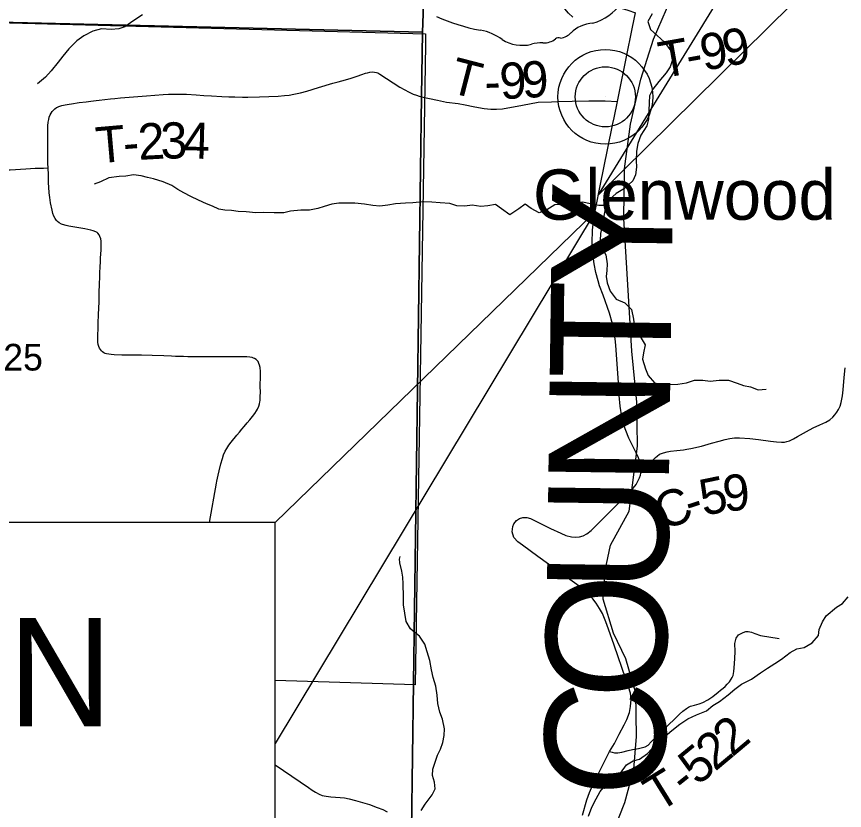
# Model space of a CAD drawing. Extents: x 0 to 34, y 0 to 22.
# Drawn here: x 4.145 to 5.445, y 16.906 to 18.153 of the extents above; entities that cross this region are included whole.
import ezdxf

# ---------------------------------------------------------------- set-up
doc = ezdxf.new("R2010")
doc.units = 0
for name, color, linetype in [('GM_X_Corporation', 7, 'Continuous'), ('GM_X_County_Road', 7, 'Continuous'), ('GM_X_County_Road_Text', 7, 'Continuous'), ('GM_X_County_Text', 7, 'Continuous'), ('GM_X_Minor_River', 7, 'Continuous'), ('GM_X_Rail_Line', 7, 'Continuous'), ('GM_X_Section_Text', 7, 'Continuous'), ('GM_X_State_Route', 7, 'Continuous'), ('GM_X_State_Shield', 7, 'Continuous'), ('GM_X_Township_Road', 7, 'Continuous'), ('GM_X_Township_Road_Text', 7, 'Continuous'), ('GM_X_Unincorporated', 7, 'Continuous'), ('GM_X_Unincorporated_Location', 7, 'Continuous'), ('GM_X_Unincorporated_Text', 7, 'Continuous'), ('SH_Data', 7, 'Continuous'), ('SH_Text', 7, 'Continuous')]:
    doc.layers.add(name, color=color, linetype=linetype)

msp = doc.modelspace()

# ---------------------------------------------------------------- linework, layer by layer
at = {"layer": 'GM_X_Corporation'}
for points in [[(4.0508, 18.1454), (4.7823, 18.128), (4.7905, 18.3604), (4.8074, 19.5455), (4.8169, 20.042), (4.8194, 20.1261), (5.11, 20.116), (6.0551, 20.0845), (6.4901, 20.0752), (6.7204, 20.0659), (7.3691, 20.0515), (7.3901, 20.051), (7.814, 20.0425), (8.4311, 20.028), (8.4311, 21.3734), (2.7987, 21.3734)], [(4.7905, 18.3604), (4.7823, 18.128), (4.7806, 18.0273), (4.765, 16.8754), (4.756, 16.2274), (4.759, 16.0879), (4.9206, 16.0842), (4.928, 16.0841), (4.9731, 16.0831), (4.975, 16.083), (5.0347, 16.0817), (5.0373, 16.0816), (6.4668, 16.045), (6.4721, 16.0449), (6.6873, 16.0404), (6.6909, 16.0403), (6.7034, 16.04), (6.9699, 16.0345), (6.9736, 16.0344), (7.8043, 16.0135), (7.8077, 16.0135), (8.4311, 16.0029), (8.4311, 20.028)], [(3.7652, 16.1115), (4.1576, 16.1007), (4.1598, 16.0996), (4.1627, 16.0987), (4.1674, 16.0981), (4.2356, 16.0972), (4.2455, 16.0972), (4.2746, 16.0965), (4.2814, 16.0964), (4.2857, 16.0964), (4.2943, 16.0963), (4.3121, 16.0959), (4.3257, 16.0953), (4.3338, 16.0949), (4.3467, 16.0944), (4.3559, 16.0941), (4.3665, 16.0934), (4.723, 16.0888), (4.759, 16.0879), (4.756, 16.2274), (4.765, 16.8754), (4.7806, 18.0273), (4.7823, 18.128), (4.7905, 18.3604)], [(4.7905, 18.3604), (4.7823, 18.128), (4.7806, 18.0273), (4.765, 16.8754), (4.756, 16.2274), (4.759, 16.0879), (4.723, 16.0888), (4.3665, 16.0934), (4.3559, 16.0941), (4.3467, 16.0944), (4.3338, 16.0949), (4.3257, 16.0953), (4.3121, 16.0959), (4.2943, 16.0963), (4.2857, 16.0964), (4.2814, 16.0964), (4.2746, 16.0965), (4.2455, 16.0972), (4.2356, 16.0972), (4.1674, 16.0981), (4.1627, 16.0987), (4.1598, 16.0996), (4.1576, 16.1007), (3.7652, 16.1115)], [(3.763, 17.3579), (3.7781, 18.1522), (4.7872, 18.1255), (4.7868, 18.1081), (4.7707, 17.1031), (4.5509, 17.1099)], [(3.7652, 16.1115), (4.1576, 16.1007), (4.1598, 16.0996), (4.1627, 16.0987), (4.1674, 16.0981), (4.2356, 16.0972), (4.2455, 16.0972), (4.2746, 16.0965), (4.2814, 16.0964), (4.2857, 16.0964), (4.2943, 16.0963), (4.3121, 16.0959), (4.3257, 16.0953), (4.3338, 16.0949), (4.3467, 16.0944), (4.3559, 16.0941), (4.3665, 16.0934), (4.723, 16.0888), (4.759, 16.0879), (4.756, 16.2274), (4.765, 16.8754), (4.7806, 18.0273), (4.7823, 18.128), (4.0508, 18.1454)]]:
    msp.add_lwpolyline(points, dxfattribs=at)
at = {"layer": 'GM_X_County_Road'}
for points in [[(5.125, 17.4354), (5.1277, 17.4396), (5.1323, 17.4445), (5.1378, 17.4501), (5.1448, 17.4572), (5.1482, 17.4604), (5.1506, 17.4625), (5.1546, 17.4652), (5.1608, 17.4675), (5.1663, 17.469), (5.1718, 17.4699), (5.1817, 17.471), (5.1921, 17.4721), (5.1975, 17.473), (5.2036, 17.4742), (5.2205, 17.4782), (5.2358, 17.4825), (5.2481, 17.4859), (5.2573, 17.4882), (5.265, 17.4899), (5.2722, 17.4908), (5.2802, 17.491), (5.2964, 17.4901), (5.3097, 17.4884), (5.3287, 17.4859), (5.3379, 17.4848), (5.3461, 17.4843), (5.3506, 17.4843), (5.3542, 17.4851), (5.3586, 17.4864), (5.3649, 17.4896), (5.3709, 17.493), (5.3849, 17.5011), (5.3956, 17.5066), (5.4061, 17.5113), (5.4155, 17.5155), (5.4216, 17.5192), (5.4265, 17.5236), (5.4297, 17.5272), (5.4327, 17.5315), (5.4352, 17.5355), (5.4378, 17.5409), (5.4397, 17.5466), (5.4418, 17.557), (5.4428, 17.5667), (5.4443, 17.5858), (5.446, 17.6012)], [(4.5509, 16.9773), (4.6034, 16.9418), (4.6093, 16.9377), (4.6141, 16.9347), (4.62, 16.9314), (4.6249, 16.9294), (4.631, 16.9281), (4.6384, 16.9274), (4.6458, 16.9269), (4.6532, 16.9262), (4.6599, 16.9254), (4.6672, 16.924), (4.6769, 16.9216), (4.6883, 16.9185), (4.6989, 16.9151), (4.7112, 16.9106), (4.7198, 16.9071), (4.7271, 16.9036)]]:
    msp.add_lwpolyline(points, dxfattribs=at)
at = {"layer": 'GM_X_Minor_River'}
for points in [[(5.1427, 18.1572), (5.1359, 18.1451), (5.1405, 18.1326), (5.1507, 18.1232), (5.1621, 18.1126), (5.172, 18.099), (5.1751, 18.0865), (5.1709, 18.0736), (5.1649, 18.0641), (5.1532, 18.0508), (5.1438, 18.0386), (5.1389, 18.028), (5.1382, 18.0177), (5.1378, 18.0045), (5.1371, 17.9916), (5.1345, 17.981), (5.1251, 17.9665), (5.1206, 17.9532), (5.1183, 17.9411), (5.118, 17.9267), (5.1184, 17.9161), (5.1165, 17.9039), (5.1124, 17.8945), (5.0996, 17.8827), (5.0863, 17.875), (5.0758, 17.8655), (5.0697, 17.8534), (5.0668, 17.8393), (5.0649, 17.8249), (5.0619, 17.812), (5.0612, 17.801), (5.0639, 17.7904), (5.07, 17.7783), (5.0723, 17.7643), (5.0719, 17.7541), (5.0708, 17.7446), (5.072, 17.7343), (5.0769, 17.7215), (5.0864, 17.7086), (5.1001, 17.703), (5.1103, 17.6928), (5.1134, 17.6776), (5.1154, 17.6625), (5.1241, 17.65), (5.1317, 17.6371), (5.1291, 17.6246), (5.1276, 17.6144), (5.1322, 17.5996), (5.1364, 17.589), (5.1467, 17.5777), (5.1584, 17.5747), (5.169, 17.5747), (5.183, 17.5755), (5.1966, 17.5775), (5.2091, 17.5817), (5.2224, 17.5817), (5.2337, 17.5803), (5.2481, 17.5814), (5.2625, 17.5815), (5.2765, 17.577), (5.286, 17.5732), (5.297, 17.5714), (5.3091, 17.5665), (5.3216, 17.5673)], [(4.3427, 18.1553), (4.3291, 18.1468), (4.3152, 18.1368), (4.3054, 18.1333), (4.2936, 18.1325), (4.2784, 18.1335), (4.2648, 18.1296), (4.2505, 18.1223), (4.2395, 18.1146), (4.2271, 18.1023), (4.2177, 18.0905), (4.2106, 18.081), (4.1993, 18.0676), (4.1903, 18.0576), (4.1778, 18.0469)], [(4.7776, 17.8613), (4.7672, 17.86), (4.7554, 17.8596), (4.7399, 17.8587), (4.7281, 17.8567), (4.7156, 17.8551), (4.7043, 17.8561), (4.6913, 17.8583), (4.6762, 17.8597), (4.6512, 17.8595), (4.6402, 17.8579), (4.6281, 17.8544), (4.6182, 17.8512), (4.605, 17.8489), (4.5913, 17.8484), (4.575, 17.8471), (4.5644, 17.8447), (4.5493, 17.8446), (4.5334, 17.8449), (4.5205, 17.8444), (4.5053, 17.8462), (4.4932, 17.8464), (4.4825, 17.8479), (4.4719, 17.8485), (4.4624, 17.8504), (4.4525, 17.8548), (4.443, 17.8586), (4.4305, 17.8645), (4.4187, 17.8701), (4.4077, 17.8761), (4.3981, 17.8813), (4.3886, 17.8873), (4.3753, 17.8929), (4.3601, 17.8981), (4.3506, 17.8999), (4.3407, 17.9025), (4.3286, 17.9039), (4.3165, 17.9023), (4.3063, 17.9015), (4.29, 17.8995), (4.2767, 17.8933), (4.2669, 17.8894)], [(5.071, 17.8559), (5.0591, 17.856), (5.0459, 17.8586), (5.0337, 17.8612), (5.019, 17.8589), (5.005, 17.8573), (4.9902, 17.8569), (4.9774, 17.8493), (4.9656, 17.8447), (4.9531, 17.8514), (4.9436, 17.8582), (4.9334, 17.8506), (4.9195, 17.8415), (4.9066, 17.8505), (4.8971, 17.8577), (4.885, 17.8554), (4.874, 17.8546), (4.8604, 17.8564), (4.849, 17.8549), (4.8361, 17.8552), (4.8251, 17.8593), (4.81, 17.8604), (4.7971, 17.8611), (4.7846, 17.8615), (4.7776, 17.8613)], [(4.7466, 17.2945), (4.7461, 17.3009)], [(4.7462, 17.3006), (4.7472, 17.3047)], [(4.7676, 17.1872), (4.7634, 17.1913), (4.7567, 17.2027), (4.7527, 17.2285), (4.7523, 17.2414), (4.7521, 17.2619), (4.7513, 17.2721), (4.7497, 17.2816), (4.7466, 17.2945)], [(5.0427, 16.8969), (5.0483, 16.9109), (5.0551, 16.9239), (5.0611, 16.9356), (5.0713, 16.9474), (5.0819, 16.9547), (5.0932, 16.9642), (5.1026, 16.9775), (5.1128, 16.9839), (5.123, 16.9863), (5.1355, 16.9954), (5.148, 17.0091), (5.1604, 17.0201), (5.174, 17.0312), (5.1865, 17.0411), (5.199, 17.0498), (5.2126, 17.0559), (5.2281, 17.0624), (5.2379, 17.0704), (5.2485, 17.0769), (5.2621, 17.0876), (5.2726, 17.0963), (5.2832, 17.1043), (5.2987, 17.112), (5.3127, 17.1219), (5.324, 17.1295), (5.3354, 17.1364), (5.346, 17.1436), (5.3596, 17.1539), (5.3701, 17.1596), (5.3815, 17.1619), (5.3943, 17.1692), (5.4038, 17.1806), (5.4053, 17.1901), (5.4105, 17.2018), (5.4162, 17.2113), (5.432, 17.225), (5.4419, 17.2311), (5.4505, 17.2414)], [(4.7802, 16.9055), (4.7863, 16.9157), (4.7976, 16.9302), (4.8021, 16.94), (4.8013, 16.9503), (4.7982, 16.9609), (4.7986, 16.9707), (4.802, 16.9814), (4.8061, 16.9924), (4.8106, 17.0022), (4.8144, 17.0125), (4.8166, 17.0235), (4.817, 17.0341), (4.8135, 17.0492), (4.8097, 17.0602), (4.8066, 17.0739), (4.8051, 17.0871), (4.8031, 17.1008), (4.7993, 17.1148), (4.7962, 17.1269), (4.7939, 17.1413), (4.7897, 17.1549), (4.7859, 17.167), (4.7775, 17.1795), (4.7676, 17.1872)]]:
    msp.add_lwpolyline(points, dxfattribs=at)
at = {"layer": 'GM_X_Rail_Line'}
msp.add_lwpolyline([(5.0755, 16.8561), (5.1001, 16.9183), (5.1142, 16.9707), (5.1181, 17.0221), (5.1174, 17.09), (5.1017, 17.1439), (5.0823, 17.1842), (5.0659, 17.2376), (5.0692, 17.2827), (5.0776, 17.3226), (5.1068, 17.3761), (5.12, 17.4779), (5.1188, 17.5469), (5.1112, 17.6272), (5.0984, 17.8358), (5.0997, 17.9137), (5.1091, 17.9837), (5.125, 18.0544), (5.1451, 18.1171), (5.1789, 18.1962)], dxfattribs=at)
at = {"layer": 'GM_X_State_Route'}
for points in [[(5.0884, 18.0194), (5.1042, 18.0973), (5.1099, 18.1258), (5.112, 18.1363), (5.1165, 18.1584)], [(5.0337, 16.8985), (5.0405, 16.9223), (5.0446, 16.9341), (5.049, 16.9451), (5.0759, 16.9982), (5.0839, 17.0112), (5.0911, 17.0257), (5.099, 17.0405), (5.1032, 17.0489), (5.1072, 17.0597), (5.1091, 17.0691), (5.1099, 17.0802), (5.1087, 17.0901), (5.1059, 17.0999), (5.1014, 17.112), (5.0831, 17.1653), (5.0744, 17.1904), (5.0702, 17.2023), (5.0647, 17.2151), (5.0604, 17.2232), (5.0552, 17.2312), (5.0497, 17.2382), (5.0424, 17.2458), (5.0344, 17.2531), (5.0244, 17.2605), (5.0134, 17.2686), (4.9636, 17.3049), (4.9391, 17.3225), (4.9321, 17.3279), (4.9255, 17.3346), (4.9232, 17.3435), (4.924, 17.3518), (4.9259, 17.3562), (4.9299, 17.3614), (4.9345, 17.3642), (4.94, 17.3657), (4.9459, 17.3658), (4.9518, 17.3643), (4.9621, 17.3592), (4.9833, 17.3485), (4.9994, 17.3411), (5.0075, 17.3379), (5.016, 17.3358), (5.0226, 17.335), (5.0289, 17.3357), (5.0347, 17.3373), (5.0402, 17.3402), (5.0472, 17.3453), (5.0707, 17.3691), (5.1102, 17.4088), (5.1175, 17.4176), (5.123, 17.4281), (5.1245, 17.4326), (5.125, 17.4354), (5.1245, 17.4513), (5.1215, 17.4595), (5.1175, 17.4676), (5.1103, 17.4819), (5.1061, 17.4904), (5.1013, 17.5024), (5.0976, 17.5135), (5.095, 17.5243), (5.0927, 17.5409), (5.0912, 17.5575), (5.0898, 17.5774), (5.0863, 17.6295), (5.0854, 17.6422), (5.0834, 17.6565), (5.0807, 17.6702), (5.0761, 17.6871), (5.0659, 17.7151), (5.0604, 17.73), (5.0579, 17.7378), (5.0544, 17.7508), (5.0517, 17.7644), (5.0496, 17.7802), (5.0489, 17.7972), (5.0491, 17.817), (5.0508, 17.8316), (5.054, 17.8499), (5.062, 17.8896), (5.0726, 17.9434), (5.0812, 17.9849), (5.0832, 17.9937), (5.0884, 18.0194)]]:
    msp.add_lwpolyline(points, dxfattribs=at)
at = {"layer": 'GM_X_State_Shield'}
for centre, major_axis, start_param, end_param in [((5.0166, 18.2068), (0.0874, 0), 5.101752, 6.440018), ((4.9291, 18.3283), (0.2524, 0), 4.195997, 4.488961), ((4.8538, 18.0702), (0.079, 0), 0.823519, 1.323587), ((5.0535, 18.1039), (0.0479, 0), 1.647645, 2.488434), ((4.9719, 18.1326), (0.0267, 0), 4.691044, 5.507374), ((4.996, 18.1132), (0.00752, 0), 1.147584, 2.315152), ((4.9928, 18.1407), (0.0282, 0), 4.937069, 5.64225), ((4.9393, 18.1476), (0.0501, 0), 4.026481, 4.996735), ((4.9682, 18.0784), (0.0412, 0), 1.495662, 1.94098)]:
    msp.add_ellipse(centre, major_axis=major_axis, ratio=0.8, start_param=start_param, end_param=end_param, dxfattribs=at)
at = {"layer": 'GM_X_Township_Road'}
for points in [[(5.0181, 18.152), (5.0117, 18.1583), (5.0058, 18.1649), (5.0036, 18.1681), (5.0029, 18.1708), (5.0035, 18.1732), (5.0053, 18.1755), (5.0092, 18.1772), (5.0114, 18.1778), (5.0146, 18.1779), (5.0199, 18.1776), (5.024, 18.1772), (5.0296, 18.1763), (5.0655, 18.1702), (5.0956, 18.1653), (5.0997, 18.1644), (5.1048, 18.1626), (5.1165, 18.1584)], [(5.0884, 18.0194), (5.1042, 18.0973), (5.1099, 18.1258), (5.112, 18.1363), (5.1165, 18.1584)], [(4.1946, 17.9148), (4.1943, 17.9223), (4.1944, 17.9329), (4.1943, 17.9416), (4.1943, 17.9533), (4.1943, 17.9595), (4.1942, 17.9645), (4.1942, 17.9738), (4.1944, 17.9813), (4.1948, 17.9868), (4.1955, 17.9911), (4.1964, 17.9947), (4.1977, 17.9982), (4.1992, 18.001), (4.2009, 18.0035), (4.203, 18.0058), (4.2053, 18.0079), (4.2079, 18.0097), (4.2095, 18.0106), (4.2112, 18.0114), (4.2159, 18.0129), (4.2213, 18.0141), (4.2275, 18.0151), (4.2311, 18.0158), (4.2434, 18.0176), (4.2545, 18.0189), (4.2618, 18.0198), (4.2699, 18.0208), (4.2748, 18.0214), (4.2926, 18.0236), (4.2994, 18.0243), (4.3081, 18.0251), (4.3285, 18.0266), (4.349, 18.0282), (4.375, 18.0303), (4.3836, 18.0308), (4.3886, 18.031), (4.396, 18.0311), (4.4016, 18.031), (4.4121, 18.0306), (4.427, 18.0298), (4.4388, 18.029), (4.4512, 18.0282), (4.4673, 18.0271), (4.4785, 18.0266), (4.4878, 18.0264), (4.4995, 18.0263), (4.5082, 18.0263), (4.5266, 18.0267), (4.5558, 18.0276), (4.5657, 18.0285), (4.5731, 18.0294), (4.5804, 18.0308), (4.5906, 18.0331), (4.6008, 18.0358), (4.6193, 18.0412), (4.6418, 18.0479), (4.6501, 18.0503), (4.6614, 18.0535), (4.6703, 18.056), (4.6797, 18.0592), (4.6871, 18.0619), (4.6929, 18.0638), (4.6959, 18.0645), (4.6999, 18.0654), (4.7037, 18.0658), (4.707, 18.0656), (4.7102, 18.065), (4.7124, 18.0642), (4.7155, 18.0625), (4.7364, 18.0487), (4.7468, 18.0419), (4.7544, 18.0376), (4.7605, 18.0344), (4.7678, 18.031), (4.7728, 18.0291), (4.7773, 18.0276), (4.7808, 18.0268)], [(4.7808, 18.0268), (4.8057, 18.0212), (4.8202, 18.0185), (4.8384, 18.016), (4.8492, 18.014), (4.8618, 18.0117), (4.8705, 18.01), (4.8791, 18.0084), (4.8897, 18.0075), (4.8986, 18.0075), (4.9079, 18.008), (4.9394, 18.0136), (4.9638, 18.0181), (4.9848, 18.0189), (4.9953, 18.0195), (5.0171, 18.0196), (5.0434, 18.0202), (5.0562, 18.0204), (5.069, 18.0202), (5.0884, 18.0194)], [(4.1946, 17.9148), (4.1876, 17.9143), (4.1815, 17.9142), (4.1745, 17.9139), (4.1596, 17.9132), (4.1348, 17.9116), (4.1286, 17.9115), (4.1237, 17.9118), (4.1213, 17.9124), (4.1183, 17.9134), (4.1156, 17.9149), (4.1131, 17.9166), (4.1107, 17.9187), (4.1087, 17.9211), (4.1073, 17.9237), (4.1059, 17.9272), (4.1048, 17.9314), (4.1036, 17.9364), (4.1021, 17.9423), (4.0976, 17.9597), (4.0957, 17.9655), (4.0936, 17.9716), (4.0919, 17.9772), (4.0906, 17.9818)], [(4.448, 17.3579), (4.4591, 17.4201), (4.4596, 17.4231), (4.4616, 17.4322), (4.4632, 17.4394), (4.4658, 17.4502), (4.4681, 17.4585), (4.4701, 17.4643), (4.4725, 17.47), (4.4749, 17.4744), (4.4782, 17.4795), (4.4819, 17.4845), (4.491, 17.4955), (4.495, 17.5002), (4.4987, 17.5045), (4.5023, 17.5087), (4.5071, 17.5144), (4.5112, 17.5191), (4.5155, 17.5244), (4.5192, 17.5294), (4.5218, 17.5336), (4.5232, 17.5363), (4.5252, 17.5409), (4.5264, 17.5444), (4.5271, 17.5474), (4.5274, 17.5499), (4.5277, 17.5548), (4.5279, 17.564), (4.5277, 17.5707), (4.5277, 17.5753), (4.528, 17.5846), (4.5278, 17.5952), (4.5273, 17.6014), (4.5266, 17.6051), (4.5256, 17.608), (4.5242, 17.6107), (4.5223, 17.6132), (4.5214, 17.6139), (4.5187, 17.6156), (4.517, 17.6163), (4.5147, 17.617), (4.5111, 17.6178), (4.5067, 17.6181), (4.5017, 17.6183), (4.4931, 17.6185), (4.485, 17.6184), (4.4764, 17.6183), (4.4689, 17.6183), (4.4646, 17.6184), (4.4515, 17.6185), (4.4434, 17.6184), (4.4279, 17.6183), (4.4217, 17.6183), (4.4137, 17.6184), (4.4069, 17.6186), (4.3946, 17.619), (4.3884, 17.6193), (4.3761, 17.62), (4.3581, 17.6205), (4.3413, 17.6207), (4.3314, 17.6208), (4.3103, 17.621), (4.2985, 17.6216), (4.2935, 17.6221), (4.2897, 17.6227), (4.2862, 17.6232), (4.2844, 17.6236), (4.2822, 17.6246), (4.2801, 17.626), (4.2782, 17.6276), (4.2767, 17.6296), (4.2754, 17.6317), (4.2742, 17.6345), (4.2734, 17.6375), (4.2728, 17.6412), (4.2726, 17.6462), (4.2727, 17.6536), (4.2731, 17.6617), (4.2734, 17.6704), (4.2738, 17.6853), (4.2741, 17.694), (4.2745, 17.7051), (4.2749, 17.7162), (4.275, 17.7212), (4.2752, 17.7305), (4.2756, 17.746), (4.2759, 17.7528), (4.2761, 17.7572), (4.2761, 17.7597), (4.2766, 17.7677), (4.277, 17.7733), (4.278, 17.7864), (4.2781, 17.792), (4.278, 17.7963), (4.2778, 17.7999), (4.2773, 17.8036), (4.276, 17.8074), (4.2749, 17.8097), (4.2729, 17.8125), (4.2714, 17.8138), (4.2697, 17.8148), (4.2655, 17.8164), (4.2619, 17.8173), (4.2571, 17.8185), (4.2522, 17.8194), (4.2332, 17.8225), (4.227, 17.8236), (4.2228, 17.8244), (4.2174, 17.8259), (4.2157, 17.8266), (4.2119, 17.8287), (4.2095, 17.8307), (4.2077, 17.8324), (4.2055, 17.8353), (4.2035, 17.8392), (4.2021, 17.8433), (4.2007, 17.8488), (4.1984, 17.8603), (4.1971, 17.8683), (4.1963, 17.8757), (4.1956, 17.885), (4.1953, 17.8918), (4.195, 17.898), (4.1951, 17.9047), (4.1946, 17.9148)], [(5.1414, 17.0135), (5.1484, 17.0211), (5.1544, 17.0267), (5.1607, 17.0323), (5.1856, 17.0571), (5.1909, 17.062), (5.1966, 17.0661), (5.1998, 17.0682), (5.2032, 17.0697), (5.2091, 17.071), (5.2168, 17.073), (5.2224, 17.0752), (5.2301, 17.0796), (5.2379, 17.0847), (5.2466, 17.0916), (5.2504, 17.0946), (5.2542, 17.0978), (5.2576, 17.1007), (5.2606, 17.1039), (5.2641, 17.1077), (5.2671, 17.1118), (5.2687, 17.1148), (5.27, 17.118), (5.2712, 17.1242), (5.2717, 17.13), (5.2722, 17.1365), (5.2729, 17.1444), (5.2731, 17.1553), (5.2729, 17.1682), (5.2737, 17.1721), (5.275, 17.1765), (5.2786, 17.1817), (5.2856, 17.1855), (5.2899, 17.1867), (5.2938, 17.1868), (5.2989, 17.186), (5.3043, 17.1839), (5.313, 17.1805), (5.3422, 17.176)], [(5.0759, 16.9982), (5.08, 16.9971), (5.084, 16.9965), (5.0892, 16.9965), (5.0952, 16.9973), (5.1053, 17), (5.1122, 17.0013), (5.1214, 17.0032), (5.1319, 17.0055), (5.1366, 17.0085), (5.1414, 17.0135)]]:
    msp.add_lwpolyline(points, dxfattribs=at)
at = {"layer": 'GM_X_Unincorporated'}
for radius in [0.0744, 0.0472]:
    msp.add_circle((5.0694, 18.0266), radius, dxfattribs=at)
at = {"layer": 'GM_X_Unincorporated_Location'}
msp.add_line((5.0694, 18.0266), (5.0694, 18.0266), dxfattribs=at)
at = {"layer": 'SH_Data'}
msp.add_lwpolyline([(1.8974, 16.6637), (4.5509, 16.6637), (4.5509, 17.3579), (1.8974, 17.3579)], close=True, dxfattribs=at)
at = {"layer": 'SH_Text'}
for points in [[(5.6652, 18.4716), (5.0586, 17.8726), (5.6652, 18.8602)], [(4.5509, 17.3579), (5.0533, 17.8458), (4.5509, 17.0108)]]:
    msp.add_lwpolyline(points, close=True, dxfattribs=at)

# ---------------------------------------------------------------- texts
at = {"layer": 'GM_X_County_Road_Text'}
for s, rotation, p in [('5', 11.5896, (5.2235, 17.3682)), ('9', 5.2261, (5.2562, 17.375)), ('C', 21.1349, (5.1602, 17.3449)), ('-', 17.9532, (5.2029, 17.3614))]:
    msp.add_text(s, height=0.0568, rotation=rotation, dxfattribs=at).set_placement(p)
at = {"layer": 'GM_X_County_Text'}
for s, rotation, p in [('Y', 89.2289, (5.1733, 17.7239)), ('T', 89.2286, (5.1714, 17.5822)), ('N', 89.2287, (5.1691, 17.4147)), ('U', 89.2287, (5.1669, 17.2472)), ('O', 89.2289, (5.1646, 17.0798)), ('C', 89.2288, (5.1626, 16.9256))]:
    msp.add_text(s, height=0.1894, rotation=rotation, dxfattribs=at).set_placement(p)
at = {"layer": 'GM_X_Section_Text'}
msp.add_text('25', height=0.04186, rotation=0, dxfattribs=at).set_placement((4.1241, 17.5968))
at = {"layer": 'GM_X_Township_Road_Text'}
for s, rotation, p in [('9', 11.1034, (5.259, 18.0737)), ('T', 10.0196, (5.1586, 18.0558)), ('9', 10.2711, (5.2237, 18.0673)), ('-', 10.0564, (5.2005, 18.0632)), ('T', 345.5466, (4.8217, 18.0343)), ('9', 3.2452, (4.9049, 18.0227)), ('9', 3.2506, (4.9395, 18.0247)), ('-', 2.1618, (4.8806, 18.0218)), ('3', 1.0981, (4.3714, 17.9294)), ('T', 5.0014, (4.2719, 17.922)), ('2', 3.1501, (4.337, 17.9275)), ('4', 358.4854, (4.4057, 17.9301)), ('-', 4.5167, (4.3141, 17.9257)), ('2', 40.0855, (5.2684, 16.9887)), ('2', 39.9316, (5.2414, 16.9661)), ('5', 39.4328, (5.214, 16.9436)), ('T', 31.87, (5.153, 16.9018)), ('-', 38.7111, (5.1952, 16.9285))]:
    msp.add_text(s, height=0.0568, rotation=rotation, dxfattribs=at).set_placement(p)
at = {"layer": 'GM_X_Unincorporated_Text'}
msp.add_text('Glenwood', height=0.07898, rotation=0, dxfattribs=at).set_placement((4.9558, 17.8336))
at = {"layer": 'SH_Text'}
msp.add_text('BEGIN ACQUISITION', height=0.17, dxfattribs=at).set_placement((2.0474, 17.0379))

doc.saveas('drawing.dxf')
